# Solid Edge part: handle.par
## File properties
Author: Deepak Maini
Template: Normal.par
Last saved by: Robert a Rhodes jr
Revision: 3
Application: Solid Edge
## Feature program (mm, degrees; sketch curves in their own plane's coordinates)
sketch for "unnamed RevolvedProtrusion 1" plane through (0, 0, 0) normal (0, -1, 0) x-axis (1, 0, 0)
  arc centre (-1.189, 48.0656) radius 3 from (0, 50.82) to (0.9047, 50.2142) cw
  arc centre (-24.0813, 24.573) radius 35.8018 from (0.9047, 50.2142) to (11.2311, 30.4727) cw
  arc centre (-24.0813, 24.573) radius 35.8018 from (11.2311, 30.4727) to (7.3882, 7.5014) cw
  arc centre (32, -5.85) radius 28 from (7.3882, 7.5014) to (8, -20.2722) ccw
  line (8, -20.2722) -> (8, -22.0927)
  arc centre (7.7288, -22.0927) radius 0.2712 from (8, -22.0927) to (7.7288, -22.364) cw
  line (7.7288, -22.364) -> (4, -22.364)
  line (4, -22.364) -> (4, -27.364)
  line (4, -27.364) -> (0, -27.364)
  line (0, -27.364) -> (0, 50.82)
revolve "unnamed RevolvedProtrusion 1" add finite 360 deg
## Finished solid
Body 1: solid body, 8 faces, 7 edges, 1 vertex.
  Faces by surface: torus 4, cylinder 2, plane 2
  Edges by curve: circle 7
Bounding box of the edges (mm; curved faces can reach further): 16.000 x 16.000 x 77.578, from (-8, -8, -27.364) to (8, 8, 50.2142).
Cylindrical faces by radius (mm): R4 x1, R8 x1
Toroidal faces (ring radius, tube radius in mm): R-24.0813 r35.8018 x1, R-1.189 r3 x1, R7.7288 r0.2712 x1, R32 r28 x1
Planar faces by outward normal: -z 2
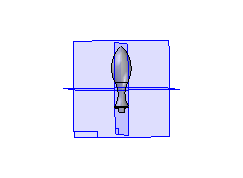
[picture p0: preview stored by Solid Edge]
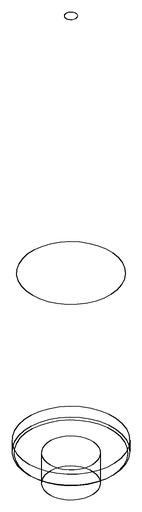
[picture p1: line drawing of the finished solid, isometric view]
